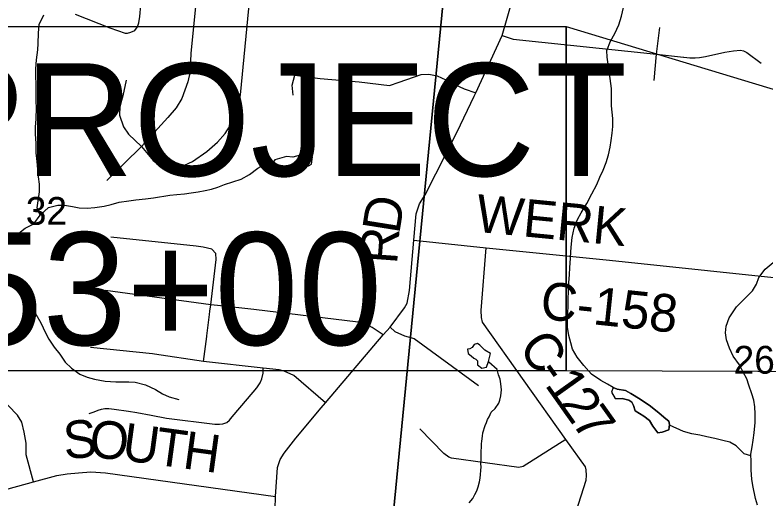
# Model space of a CAD drawing. Extents: x 0 to 43.4, y -8.1 to 22.
# Drawn here: x 4.286 to 5.419, y 18.697 to 19.427 of the extents above; entities that cross this region are included whole.
import ezdxf

# ---------------------------------------------------------------- set-up
doc = ezdxf.new("R2010")
doc.units = 0
for name, color, linetype in [('GM_X_Corporation', 7, 'Continuous'), ('GM_X_County_Road', 7, 'Continuous'), ('GM_X_County_Road_Text', 7, 'Continuous'), ('GM_X_Minor_Lake', 7, 'Continuous'), ('GM_X_Minor_River', 7, 'Continuous'), ('GM_X_Section_Text', 7, 'Continuous'), ('GM_X_Township_Road', 7, 'Continuous'), ('SH_Masking', 7, 'Continuous'), ('SH_Text', 7, 'Continuous')]:
    doc.layers.add(name, color=color, linetype=linetype)

msp = doc.modelspace()

# ---------------------------------------------------------------- linework, layer by layer
at = {"layer": 'GM_X_Corporation'}
for points in [[(3.9403, 19.703), (4.9462, 19.5972), (4.8473, 18.579), (3.8378, 18.6959)], [(5.9616, 19.4927), (5.8893, 18.4791), (4.8473, 18.579), (4.9462, 19.5972)]]:
    msp.add_lwpolyline(points, close=True, dxfattribs=at)
at = {"layer": 'GM_X_County_Road'}
for points in [[(4.8412, 18.9443), (4.8517, 18.9555), (4.8735, 18.9849), (4.8771, 18.9917), (4.8807, 19.0109), (4.8872, 19.0868), (4.8907, 19.1269), (4.8957, 19.1416), (4.9044, 19.1555), (4.9529, 19.2503), (4.9786, 19.304), (4.9807, 19.309), (5.0206, 19.3955), (5.0483, 19.4922), (5.0629, 19.5365), (5.074, 19.6019), (5.0812, 19.673), (5.0855, 19.6927)], [(4.8872, 19.0868), (4.9964, 19.0755), (5.1827, 19.0567), (5.4785, 19.0255), (5.6484, 19.0084), (5.672, 19.006), (5.9168, 18.9788)], [(5.1249, 18.6542), (5.1472, 18.7247), (5.148, 18.7319), (5.1476, 18.7405), (5.1462, 18.7448), (5.1166, 18.7862), (4.9908, 18.9633), (4.9895, 18.9702), (4.9891, 18.9809), (4.9964, 19.0755)], [(4.7476, 18.8342), (4.7539, 18.8418), (4.8412, 18.9443)], [(4.6787, 18.7001), (4.6817, 18.7438), (4.6855, 18.7562), (4.6915, 18.7655), (4.7091, 18.7882), (4.7476, 18.8342)], [(4.2601, 18.7077), (4.3134, 18.7223), (4.3485, 18.732), (4.3642, 18.7346), (4.3813, 18.7361), (4.3999, 18.7375), (4.4223, 18.7362), (4.6787, 18.7001)], [(4.6764, 18.6236), (4.6787, 18.7001)]]:
    msp.add_lwpolyline(points, dxfattribs=at)
at = {"layer": 'GM_X_Minor_Lake'}
for points in [[(4.7051, 19.1923), (4.7147, 19.1947), (4.7285, 19.1993), (4.7331, 19.2014), (4.7346, 19.2128), (4.7293, 19.2167), (4.7214, 19.2169), (4.7049, 19.212), (4.695, 19.2131), (4.6774, 19.2082), (4.675, 19.2047)], [(4.675, 19.2047), (4.6752, 19.1942), (4.6835, 19.1947), (4.7051, 19.1923)], [(5, 18.904), (5.0029, 18.9161), (4.9943, 18.9209), (4.9869, 18.9283), (4.9832, 18.931), (4.9782, 18.9293), (4.9754, 18.9252), (4.9716, 18.923), (4.9685, 18.9227), (4.9691, 18.9158), (4.974, 18.9123), (4.9777, 18.9091), (4.981, 18.9075), (4.9833, 18.9048)], [(4.9833, 18.9048), (4.9835, 18.8991), (4.9902, 18.8936), (4.9971, 18.8953), (5, 18.904)], [(5.1882, 18.8648), (5.1857, 18.8576), (5.1911, 18.848), (5.2018, 18.8481)], [(5.188, 18.8649), (5.1941, 18.862), (5.2066, 18.8601), (5.2149, 18.8554), (5.2287, 18.847), (5.2444, 18.8363), (5.2574, 18.8261), (5.2678, 18.8175), (5.2719, 18.8139), (5.2733, 18.809), (5.2719, 18.8006), (5.262, 18.7971), (5.2555, 18.7961), (5.2478, 18.8066), (5.2427, 18.8147), (5.2345, 18.8214), (5.2281, 18.8254), (5.2214, 18.8297), (5.2186, 18.8374), (5.2161, 18.8428), (5.212, 18.8456), (5.2078, 18.8468), (5.2018, 18.8481)], [(5.2018, 18.8481), (5.2078, 18.8468), (5.212, 18.8456), (5.2161, 18.8428), (5.2186, 18.8374), (5.2214, 18.8297), (5.2281, 18.8254), (5.2345, 18.8214), (5.2427, 18.8147), (5.2478, 18.8066), (5.2555, 18.7961), (5.262, 18.7971), (5.2719, 18.8006), (5.2733, 18.809), (5.2719, 18.8139), (5.2678, 18.8175), (5.2574, 18.8261), (5.2444, 18.8363), (5.2287, 18.847), (5.2149, 18.8554), (5.2066, 18.8601), (5.1941, 18.862), (5.1882, 18.8648)]]:
    msp.add_lwpolyline(points, dxfattribs=at)
at = {"layer": 'GM_X_Minor_River'}
for points in [[(5.188, 18.8649), (5.1796, 18.8695), (5.1695, 18.8751), (5.1554, 18.8847), (5.144, 18.8979), (5.1337, 18.9104), (5.1269, 18.9224), (5.1241, 18.9323), (5.121, 18.9431), (5.1191, 18.9557), (5.119, 18.9663), (5.1197, 18.9773), (5.12, 18.9876), (5.1203, 18.9986), (5.1206, 19.0096), (5.1214, 19.0229), (5.1221, 19.0347), (5.1228, 19.0457), (5.1236, 19.0593), (5.1243, 19.0696), (5.1254, 19.0813), (5.1264, 19.0912), (5.1295, 19.1052), (5.1344, 19.118), (5.14, 19.1284), (5.1484, 19.1423), (5.156, 19.1569), (5.1637, 19.1707), (5.1678, 19.182), (5.173, 19.1925), (5.1775, 19.2042), (5.1813, 19.2158), (5.1835, 19.2272), (5.185, 19.2374), (5.1868, 19.2484), (5.1875, 19.2583), (5.1878, 19.2704), (5.1866, 19.2799), (5.1857, 19.2895), (5.1857, 19.3028), (5.1857, 19.3157), (5.1826, 19.3386), (5.1807, 19.3524), (5.1791, 19.363), (5.1786, 19.3729), (5.184, 19.3869), (5.1904, 19.3988), (5.1968, 19.412), (5.2006, 19.4248), (5.2037, 19.438)], [(4.3234, 19.1247), (4.3191, 19.1355), (4.3206, 19.1465), (4.3225, 19.1601), (4.3224, 19.1715), (4.3212, 19.1826), (4.32, 19.1933), (4.3189, 19.2058), (4.3177, 19.2188), (4.3174, 19.2329), (4.3163, 19.2474), (4.3166, 19.2572), (4.3173, 19.2701), (4.3182, 19.2865), (4.3177, 19.2964), (4.3177, 19.31), (4.3173, 19.3234), (4.3169, 19.3333), (4.3168, 19.3454), (4.318, 19.3591), (4.3199, 19.3742), (4.3206, 19.3837), (4.321, 19.3993), (4.3222, 19.4122), (4.3291, 19.4268)], [(4.2826, 19.0818), (4.2887, 19.0957), (4.3011, 19.1048), (4.3139, 19.1117), (4.3234, 19.1247), (4.3362, 19.1362), (4.35, 19.1399), (4.3603, 19.1397), (4.3724, 19.1378), (4.3825, 19.1356), (4.3943, 19.1353), (4.4061, 19.1361), (4.4202, 19.1383), (4.4305, 19.1407), (4.4428, 19.1441), (4.4573, 19.1464), (4.468, 19.1476), (4.4824, 19.1495), (4.4943, 19.1507), (4.5191, 19.1549), (4.5297, 19.1557), (4.5412, 19.1569), (4.5514, 19.1582), (4.5621, 19.1598), (4.5724, 19.1617), (4.582, 19.1638), (4.5916, 19.1669), (4.6016, 19.1708), (4.6269, 19.1792), (4.6396, 19.1861), (4.652, 19.1956), (4.6644, 19.2028), (4.6739, 19.2045), (4.675, 19.2047)], [(5.4061, 18.6874), (5.4029, 18.697), (5.3989, 18.7169), (5.3973, 18.7264), (5.3966, 18.7402), (5.3962, 18.7531), (5.3957, 18.7641), (5.398, 18.7751), (5.3994, 18.7853), (5.4008, 18.7963), (5.4024, 18.8118), (5.4024, 18.8248), (5.402, 18.8354), (5.4004, 18.8454), (5.3976, 18.8549), (5.393, 18.868), (5.3899, 18.8776), (5.3841, 18.888), (5.3787, 18.8988), (5.3693, 18.912), (5.3639, 18.924), (5.3593, 18.9366), (5.3577, 18.947), (5.3588, 18.9572), (5.363, 18.97), (5.3744, 18.9864), (5.3873, 18.9993), (5.3983, 19.0104), (5.4043, 19.0205), (5.408, 19.0307), (5.4175, 19.0433), (5.4295, 19.0533)], [(4.2797, 19.0336), (4.2881, 19.0212), (4.2954, 19.0111), (4.3015, 19.0003), (4.3099, 18.9864), (4.3168, 18.9755), (4.3244, 18.962), (4.3315, 18.9473), (4.3366, 18.9377), (4.3446, 18.9257), (4.353, 18.9148), (4.3614, 18.9031), (4.371, 18.8937), (4.3836, 18.8846), (4.3942, 18.8805), (4.4055, 18.8772), (4.4217, 18.8744), (4.4376, 18.8732), (4.4574, 18.8734), (4.4669, 18.8728), (4.4823, 18.8689), (4.4977, 18.8616), (4.5081, 18.8549), (4.5182, 18.8504), (4.5326, 18.8466)], [(4.9765, 18.6971), (4.9794, 18.7031), (4.9826, 18.7087), (4.9843, 18.7147), (4.9865, 18.7226), (4.9875, 18.7279), (4.988, 18.7332), (4.9886, 18.7397), (4.9888, 18.745), (4.9886, 18.7495), (4.9888, 18.7571), (4.9887, 18.764), (4.9889, 18.7693), (4.9894, 18.7742), (4.9896, 18.7795), (4.9901, 18.7837), (4.9908, 18.7913), (4.9917, 18.7962), (4.9951, 18.8075), (4.9972, 18.812), (4.9985, 18.8165), (5.0009, 18.8206), (5.0042, 18.8273), (5.0101, 18.8328), (5.0157, 18.8413), (5.017, 18.8455), (5.0187, 18.8523), (5.0194, 18.861), (5.0186, 18.8701), (5.0177, 18.8774), (5.0149, 18.8839), (5.0129, 18.892), (5.0003, 18.9031), (5, 18.904)], [(5.3958, 18.7615), (5.3859, 18.7648), (5.3737, 18.7765), (5.364, 18.7821), (5.3538, 18.7847), (5.3417, 18.7877), (5.3297, 18.7904), (5.3191, 18.7926), (5.3066, 18.7948), (5.2942, 18.7982), (5.2731, 18.808)], [(4.971, 18.6905), (4.9765, 18.6971)]]:
    msp.add_lwpolyline(points, dxfattribs=at)
at = {"layer": 'GM_X_Township_Road'}
msp.add_line((4.57, 18.904), (4.575, 18.9418), dxfattribs=at)
for points in [[(4.5841, 19.7041), (4.5597, 19.4597), (4.5507, 19.3692), (4.5505, 19.3565), (4.5503, 19.3514)], [(4.3763, 19.4277), (4.4288, 19.4075), (4.4517, 19.3994), (4.4553, 19.3994), (4.4602, 19.4005), (4.4665, 19.4034), (4.4702, 19.409), (4.4722, 19.4148), (4.4737, 19.4243), (4.4756, 19.4415), (4.4787, 19.4541), (4.4876, 19.4729), (4.4927, 19.4862), (4.4946, 19.4941), (4.4944, 19.5025), (4.486, 19.5508), (4.4833, 19.568)], [(4.4534, 19.3282), (4.4483, 19.3049), (4.4436, 19.2886), (4.4434, 19.2756), (4.4491, 19.2578), (4.457, 19.2469), (4.4763, 19.228), (4.4939, 19.2069), (4.504, 19.1998), (4.513, 19.1958), (4.5247, 19.1947), (4.535, 19.1971), (4.5535, 19.2057), (4.5751, 19.2207), (4.5911, 19.2348), (4.6028, 19.2478), (4.6108, 19.2605), (4.6214, 19.2835), (4.6258, 19.306), (4.64, 19.4527), (4.642, 19.478), (4.6508, 19.5688)], [(5.2502, 19.3278), (5.2537, 19.3676), (5.2587, 19.4079)], [(5.0206, 19.3955), (5.0372, 19.39), (5.2537, 19.3676), (5.294, 19.3629), (5.295, 19.3628)], [(5.295, 19.3628), (5.3037, 19.3619), (5.3117, 19.3622), (5.3184, 19.3626), (5.3273, 19.3639), (5.3566, 19.3703), (5.3696, 19.3727), (5.3802, 19.3735), (5.3848, 19.3724), (5.39, 19.3702), (5.4112, 19.3541)], [(4.5503, 19.3514), (4.55, 19.3412), (4.5463, 19.3256), (4.5373, 19.3006), (4.5289, 19.2864), (4.5162, 19.2719), (4.4763, 19.228), (4.424, 19.1772)], [(4.7054, 19.3059), (4.704, 19.321), (4.7077, 19.3359), (4.746, 19.3309), (4.8048, 19.3259), (4.8504, 19.3204), (4.8654, 19.3255), (4.8982, 19.3369), (4.9101, 19.3373), (4.9224, 19.335), (4.9356, 19.3286), (4.9481, 19.3221), (4.9634, 19.315), (4.9807, 19.309)], [(4.5797, 18.9797), (4.5811, 18.9894), (4.5891, 19.0577), (4.5888, 19.0666), (4.5827, 19.0736), (4.5693, 19.0765), (4.5589, 19.0777), (4.4303, 19.0917)], [(4.591, 18.9883), (4.5811, 18.9894), (4.4222, 19.0109)], [(4.8412, 18.9443), (4.8247, 18.9554), (4.8152, 18.9603), (4.8031, 18.9631), (4.6459, 18.9821), (4.591, 18.9883)], [(4.575, 18.9418), (4.5751, 18.9427), (4.5789, 18.9748), (4.5797, 18.9797)], [(4.8517, 18.9555), (4.8587, 18.9494), (4.8733, 18.9427), (4.8876, 18.9386), (4.9851, 18.8678)], [(4.3134, 18.7223), (4.3026, 18.7633), (4.3023, 18.7805), (4.2994, 18.7972), (4.2957, 18.8125), (4.2893, 18.8227), (4.2609, 18.8518), (4.2493, 18.8637), (4.2287, 18.8852), (4.218, 18.8956), (4.2047, 18.9062), (4.191, 18.9135), (4.1798, 18.9178), (4.1675, 18.9202), (4.1318, 18.9227), (4.0964, 18.9235), (4.0624, 18.9241), (4.0167, 18.9238), (3.994, 18.9256), (3.8669, 18.9333), (3.8602, 18.9337)], [(4.4961, 18.9149), (4.493, 18.9154), (4.3997, 18.9252)], [(4.7539, 18.8418), (4.7061, 18.8826), (4.6917, 18.8894), (4.684, 18.8913), (4.6599, 18.8938), (4.57, 18.904), (4.4961, 18.9149)], [(4.3976, 18.8254), (4.405, 18.8278), (4.4112, 18.8304), (4.4159, 18.8322), (4.421, 18.8332), (4.4272, 18.8331), (4.4353, 18.8322), (4.4566, 18.8291), (4.4695, 18.8271), (4.491, 18.8231), (4.514, 18.8183), (4.5869, 18.8095), (4.5941, 18.8093), (4.5992, 18.8098), (4.605, 18.8117), (4.6091, 18.8152), (4.6133, 18.8204), (4.6363, 18.8476), (4.6505, 18.8642), (4.6555, 18.8717), (4.6581, 18.8778), (4.6599, 18.8862), (4.6599, 18.8938)], [(5.1166, 18.7862), (5.0523, 18.7456), (5.0458, 18.7439), (4.9443, 18.7582), (4.9402, 18.7598), (4.9328, 18.765), (4.8965, 18.8023)]]:
    msp.add_lwpolyline(points, dxfattribs=at)
at = {"layer": 'SH_Masking'}
msp.add_lwpolyline([(3.3595, 19.4094), (5.117, 19.4094), (5.117, 18.89), (3.3595, 18.89)], close=True, dxfattribs=at)
at = {"layer": 'SH_Text'}
for points in [[(3.3595, 19.4094), (5.117, 19.4094), (5.117, 18.89), (3.3595, 18.89)], [(5.117, 19.4094), (6.8528, 18.8836), (5.117, 18.89)]]:
    msp.add_lwpolyline(points, close=True, dxfattribs=at)

# ---------------------------------------------------------------- texts
at = {"layer": 'GM_X_County_Road_Text'}
for s, height, rotation, p in [('D', 0.0568, 80.9539, (4.8653, 19.0951)), ('WERK', 0.05682, 354.4546, (4.9792, 19.0998)), ('R', 0.0568, 85.8454, (4.862, 19.0498)), ('C-158', 0.05682, 353.9906, (5.0766, 18.9686)), ('C', 0.0568, 305.3822, (5.0437, 18.9253)), ('1', 0.0568, 305.3825, (5.0839, 18.8687)), ('-', 0.0568, 305.3823, (5.0705, 18.8875)), ('2', 0.0568, 305.3916, (5.104, 18.8403)), ('7', 0.0568, 305.441, (5.1241, 18.812)), ('S', 0.0568, 4.3899, (4.3604, 18.7566)), ('O', 0.0568, 355.1932, (4.3963, 18.7595)), ('U', 0.0568, 352.2832, (4.4453, 18.7554)), ('T', 0.0568, 352.2235, (4.4949, 18.7487)), ('H', 0.0568, 352.2207, (4.537, 18.743))]:
    msp.add_text(s, height=height, rotation=rotation, dxfattribs=at).set_placement(p)
at = {"layer": 'GM_X_Section_Text'}
for s, p in [('32', (4.3018, 19.1102)), ('26', (5.3698, 18.8856))]:
    msp.add_text(s, height=0.04186, rotation=0, dxfattribs=at).set_placement(p)
at = {"layer": 'SH_Text'}
for s, p in [('BEGIN PROJECT', (3.3778, 19.1837)), ('STA. 53+00', (3.6326, 18.9287))]:
    msp.add_text(s, height=0.17, dxfattribs=at).set_placement(p)

doc.saveas('drawing.dxf')
